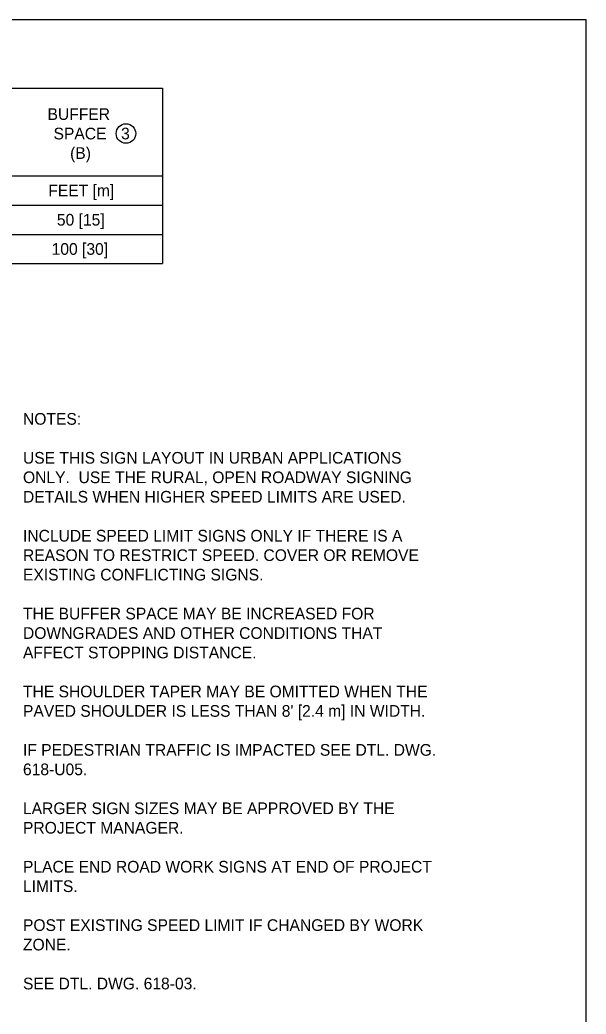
# Model space of a CAD drawing. Extents: x 49991.4 to 50021, y 49987.6 to 50011.4.
# Drawn here: x 50005.71 to 50008.61, y 50006.16 to 50011.26 of the extents above; entities that cross this region are included whole.
import ezdxf

# ---------------------------------------------------------------- set-up
doc = ezdxf.new("R2010")
doc.units = 0
doc.layers.add('Level 1', color=7, linetype='Continuous')
doc.layers.add('Level 2', color=7, linetype='Continuous')

msp = doc.modelspace()

# ---------------------------------------------------------------- linework, layer by layer
at = {"layer": 'Level 1'}
msp.add_lwpolyline([(50008.6146, 50011.2628), (50000.3356, 50011.2628), (50000.3356, 50000.0624), (50008.6146, 50000.0624)], close=True, dxfattribs=at)
at = {"layer": 'Level 2'}
for p, q in [((50002.5101, 50010.9113), (50006.4401, 50010.9113)), ((50006.4401, 50010.9113), (50006.4401, 50010.0113)), ((50002.5101, 50010.4613), (50006.4401, 50010.4613)), ((50002.5101, 50010.3113), (50006.4401, 50010.3113)), ((50002.5101, 50010.1613), (50006.4401, 50010.1613)), ((50002.5101, 50010.0113), (50006.4401, 50010.0113))]:
    msp.add_line(p, q, dxfattribs=at)
msp.add_circle((50006.2517, 50010.679), 0.0501, dxfattribs=at)

# ---------------------------------------------------------------- texts
for s, p in [('BUFFER', (50005.849, 50010.749)), ('SPACE', (50005.8798, 50010.649)), ('3', (50006.2267, 50010.6491)), ('(B)', (50005.965, 50010.549)), ('FEET [m]', (50005.8528, 50010.3563)), ('50 [15]', (50005.8969, 50010.2063)), ('100 [30]', (50005.87, 50010.0563)), ('NOTES:', (50005.7229, 50009.1836)), ('USE THIS SIGN LAYOUT IN URBAN APPLICATIONS', (50005.7229, 50008.9836)), ('ONLY.  USE THE RURAL, OPEN ROADWAY SIGNING', (50005.7229, 50008.8836)), ('DETAILS WHEN HIGHER SPEED LIMITS ARE USED.', (50005.7229, 50008.7836)), ('INCLUDE SPEED LIMIT SIGNS ONLY IF THERE IS A', (50005.7229, 50008.5836)), ('REASON TO RESTRICT SPEED. COVER OR REMOVE', (50005.7229, 50008.4836)), ('EXISTING CONFLICTING SIGNS.', (50005.7229, 50008.3836)), ('THE BUFFER SPACE MAY BE INCREASED FOR', (50005.7229, 50008.1836)), ('DOWNGRADES AND OTHER CONDITIONS THAT', (50005.7229, 50008.0836)), ('AFFECT STOPPING DISTANCE. ', (50005.7229, 50007.9836)), ('THE SHOULDER TAPER MAY BE OMITTED WHEN THE ', (50005.7229, 50007.7836)), ("PAVED SHOULDER IS LESS THAN 8' [2.4 m] IN WIDTH.", (50005.7229, 50007.6836)), ('IF PEDESTRIAN TRAFFIC IS IMPACTED SEE DTL. DWG.', (50005.7229, 50007.4836)), ('618-U05.', (50005.7229, 50007.3836)), ('LARGER SIGN SIZES MAY BE APPROVED BY THE', (50005.7229, 50007.1836)), ('PROJECT MANAGER.', (50005.7229, 50007.0836)), ('PLACE END ROAD WORK SIGNS AT END OF PROJECT', (50005.7229, 50006.8836)), ('LIMITS.', (50005.7229, 50006.7836)), ('POST EXISTING SPEED LIMIT IF CHANGED BY WORK', (50005.7229, 50006.5836)), ('ZONE.', (50005.7229, 50006.4836)), ('SEE DTL. DWG. 618-03.', (50005.7229, 50006.2836))]:
    msp.add_text(s, height=0.06, dxfattribs=at).set_placement(p)

doc.saveas('drawing.dxf')
